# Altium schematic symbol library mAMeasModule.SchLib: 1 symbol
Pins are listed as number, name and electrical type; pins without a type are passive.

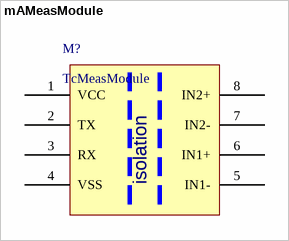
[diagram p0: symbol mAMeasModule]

## mAMeasModule
designator M?, comment TcMeasModule
2路隔离20mA,10V测量模块
pins: 1 VCC, 2 TX, 3 RX, 4 VSS, 5 IN1-, 6 IN1+, 7 IN2-, 8 IN2+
